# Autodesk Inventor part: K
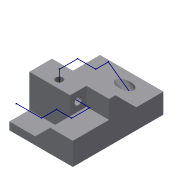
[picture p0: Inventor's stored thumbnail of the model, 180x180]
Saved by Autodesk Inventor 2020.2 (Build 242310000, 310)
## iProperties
Created: 2014-07
Part Number: K
Material: Ogólny
Document SubType Name: Modeling
Designer: F.Stasiak
Density: 1 g/cm^3
Appearance: Domyślna
Catalog Web Link: www.expertbooks.pl
Manager: www.cadconsulting.pl
Company: Fabian Stasiak CAD Consulting
Author: F.Stasiak
Subject: Zbiór ćwiczeń. Autodesk Inventor 2020. Kurs Professional
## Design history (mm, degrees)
derived "Konstrukcja_3.ipt"
feature "Bryła1::Konstrukcja_3.ipt" dims "d0" = 10
tag "Bryła wyprowadzona1"
sketch "Szkic 3D3"
node "Bryła1"
